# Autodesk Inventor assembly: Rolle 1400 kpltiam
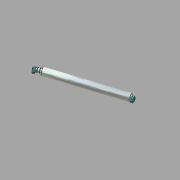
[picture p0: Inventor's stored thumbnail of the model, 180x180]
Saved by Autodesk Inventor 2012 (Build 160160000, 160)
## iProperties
Company: CAD-Verlag
Created: 2004-12
Part Number: Rolle 1400 kpltiam
Document SubType Name: Assembly
Designer: jukr
Manufacturer: Standard
Standards Organization: Custom
Author: Jürgen Kronas
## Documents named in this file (8)
- C:\DemoDaten2012\CAD Daten\Daten Vault 2012 Inventor\Kapitel 6\6.4\Rollenbahn\Rollenbahn 1400\Rolle 1400 kpltiam.iam
- C:\DemoDaten2012\CAD Daten\Daten Vault 2012 Inventor\Kapitel 6\6.4\Rollenbahn\Bibliotheken\local.AFNOR.12.490.8.ipt
- C:\DemoDaten2012\CAD Daten\Daten Vault 2012 Inventor\Kapitel 6\6.4\Rollenbahn\Bibliotheken\local.DIN.162.250.8.ipt
- C:\DemoDaten2012\CAD Daten\Daten Vault 2012 Inventor\Kapitel 6\6.4\Rollenbahn\Rollenbahn 1400\pase30.iam
- C:\DemoDaten2012\CAD Daten\Daten Vault 2012 Inventor\Kapitel 6\6.4\Rollenbahn\Bibliotheken\local.AFNOR.63.110.8.ipt
- C:\DemoDaten2012\CAD Daten\Daten Vault 2012 Inventor\Kapitel 6\6.4\Rollenbahn\Bibliotheken\local.DIN.177.30.8.ipt
- C:\DemoDaten2012\CAD Daten\Daten Vault 2012 Inventor\Kapitel 6\6.4\Rollenbahn\Rollenbahn 1400\Rolle_3-4_z14_1400.iam
- C:\DemoDaten2012\CAD Daten\Daten Vault 2012 Inventor\Kapitel 6\6.4\Rollenbahn\Rollenbahn 1400\Lagergruppe.iam
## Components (11 placed, 7 different names)
1. NF EN 24014  (Regelgewinde) M12 x 50:3
2. NF EN 24014  (Regelgewinde) M12 x 50:4
3. DIN 125-1  B B 13:3
4. DIN 125-1  B B 13:4
5. NF EN 24032  (Regelgewinde) M12:4
6. DIN 434 14:3
7. NF EN 24032  (Regelgewinde) M12:3
8. DIN 434 14:4
9. pase30:1 [sub-assembly] — Fluchtend:1
10. Rolle_3-4_z14_1400:1 [sub-assembly] — Passend:1
11. Lagergruppe:1 [sub-assembly] — Passend:1, Fluchtend:1
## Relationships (2: Mate 1, Flush 1)
- Passend:1 [Mate]: Rolle_3-4_z14_1400:1 ↔ Lagergruppe:1
- Fluchtend:1 [Flush]: pase30:1 ↔ Lagergruppe:1
